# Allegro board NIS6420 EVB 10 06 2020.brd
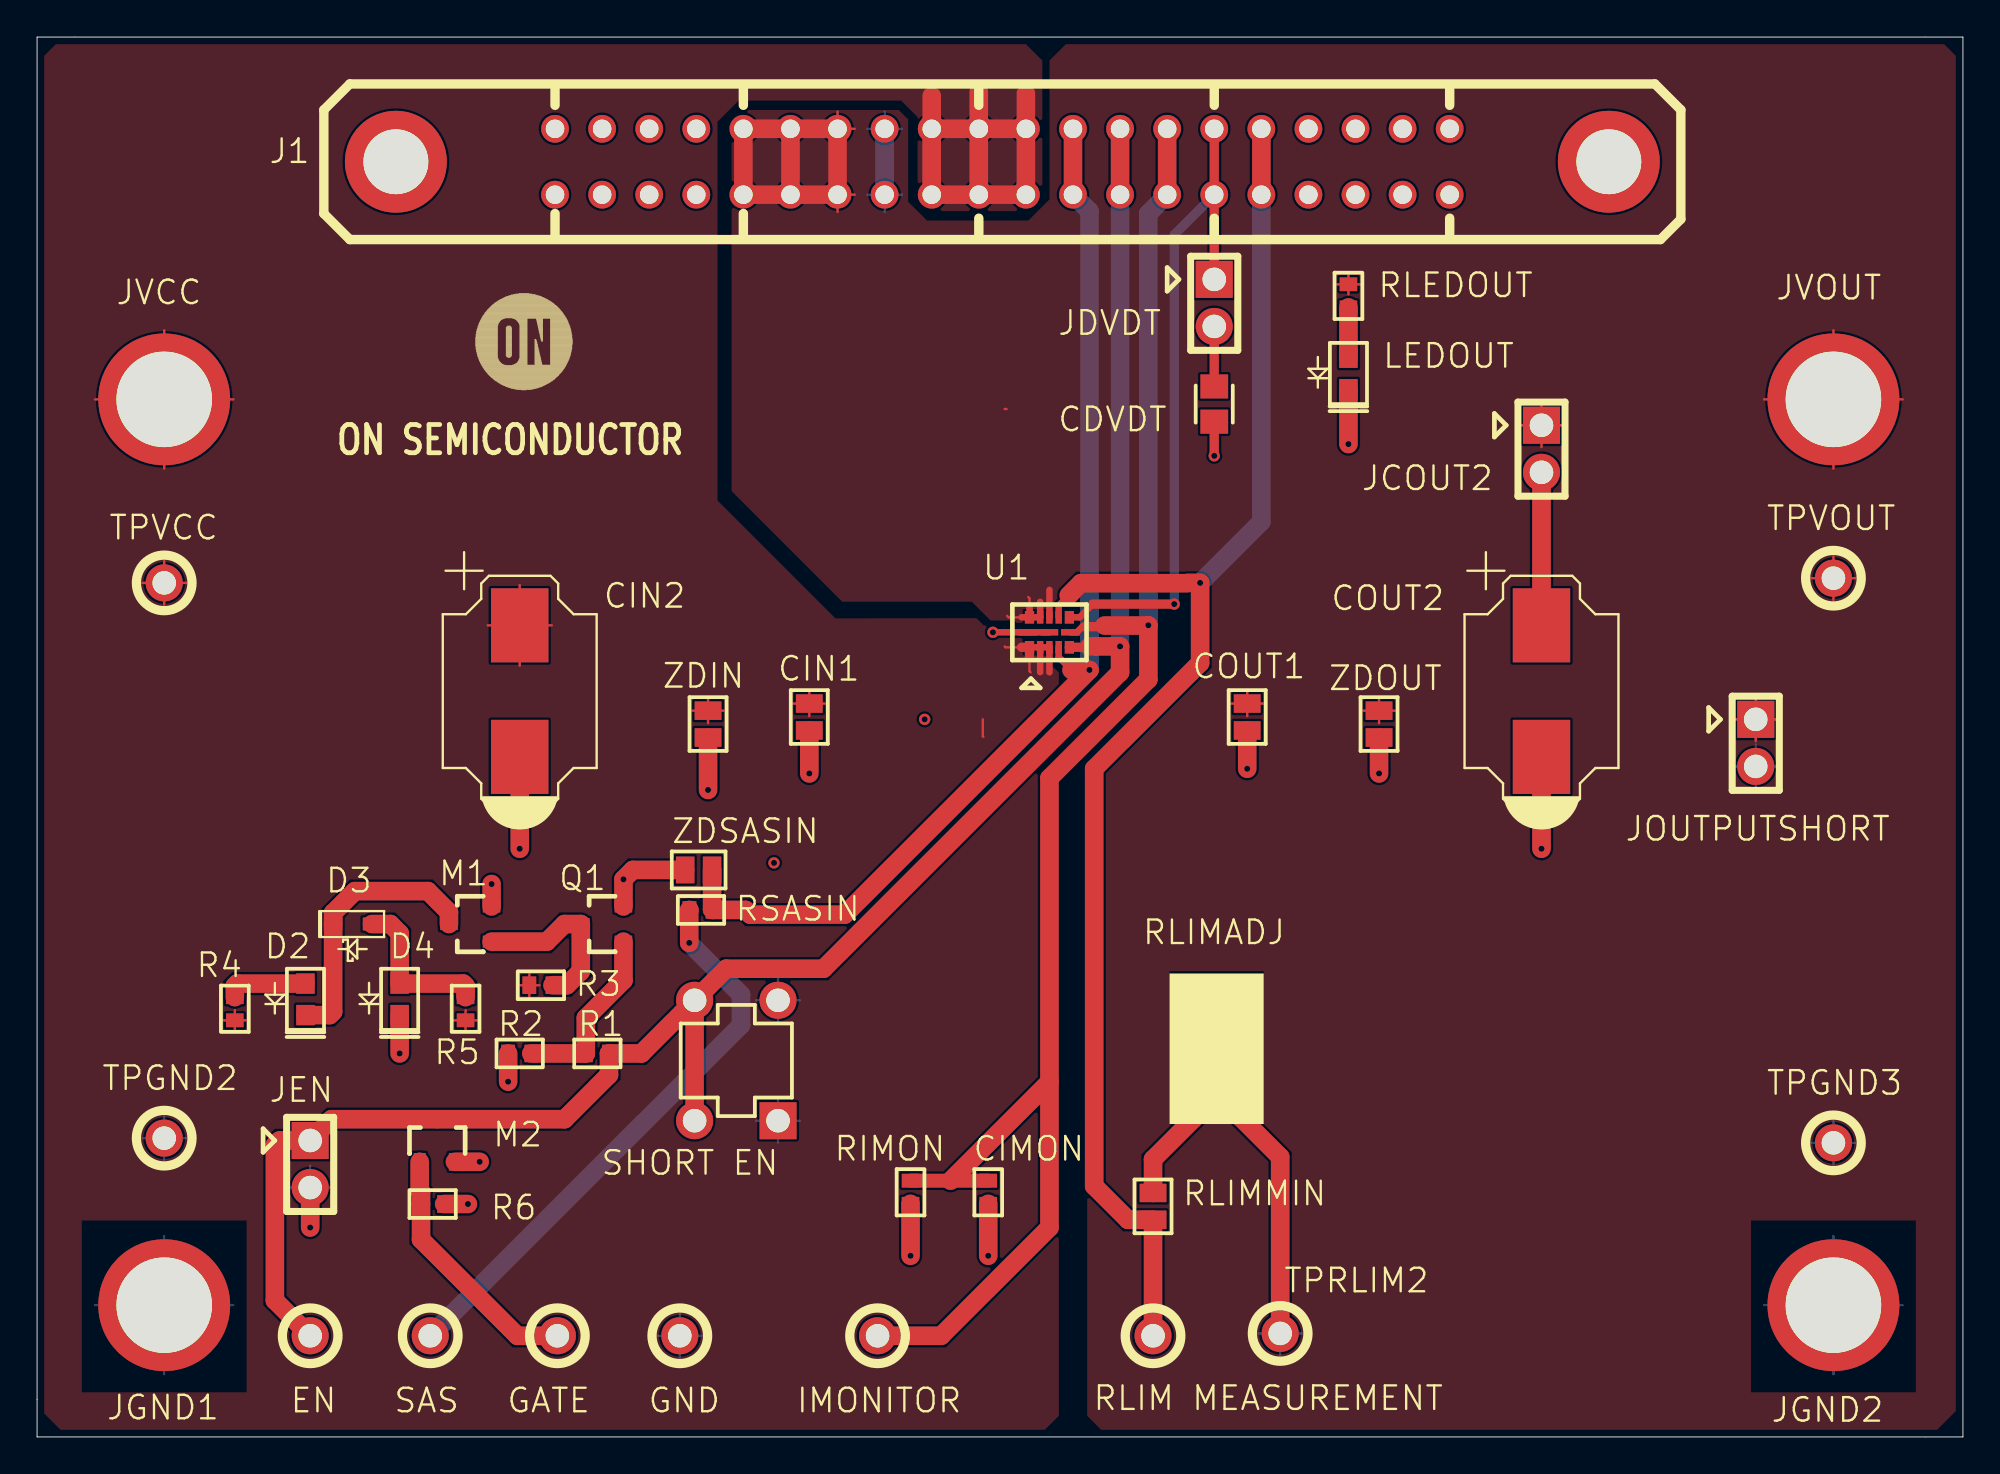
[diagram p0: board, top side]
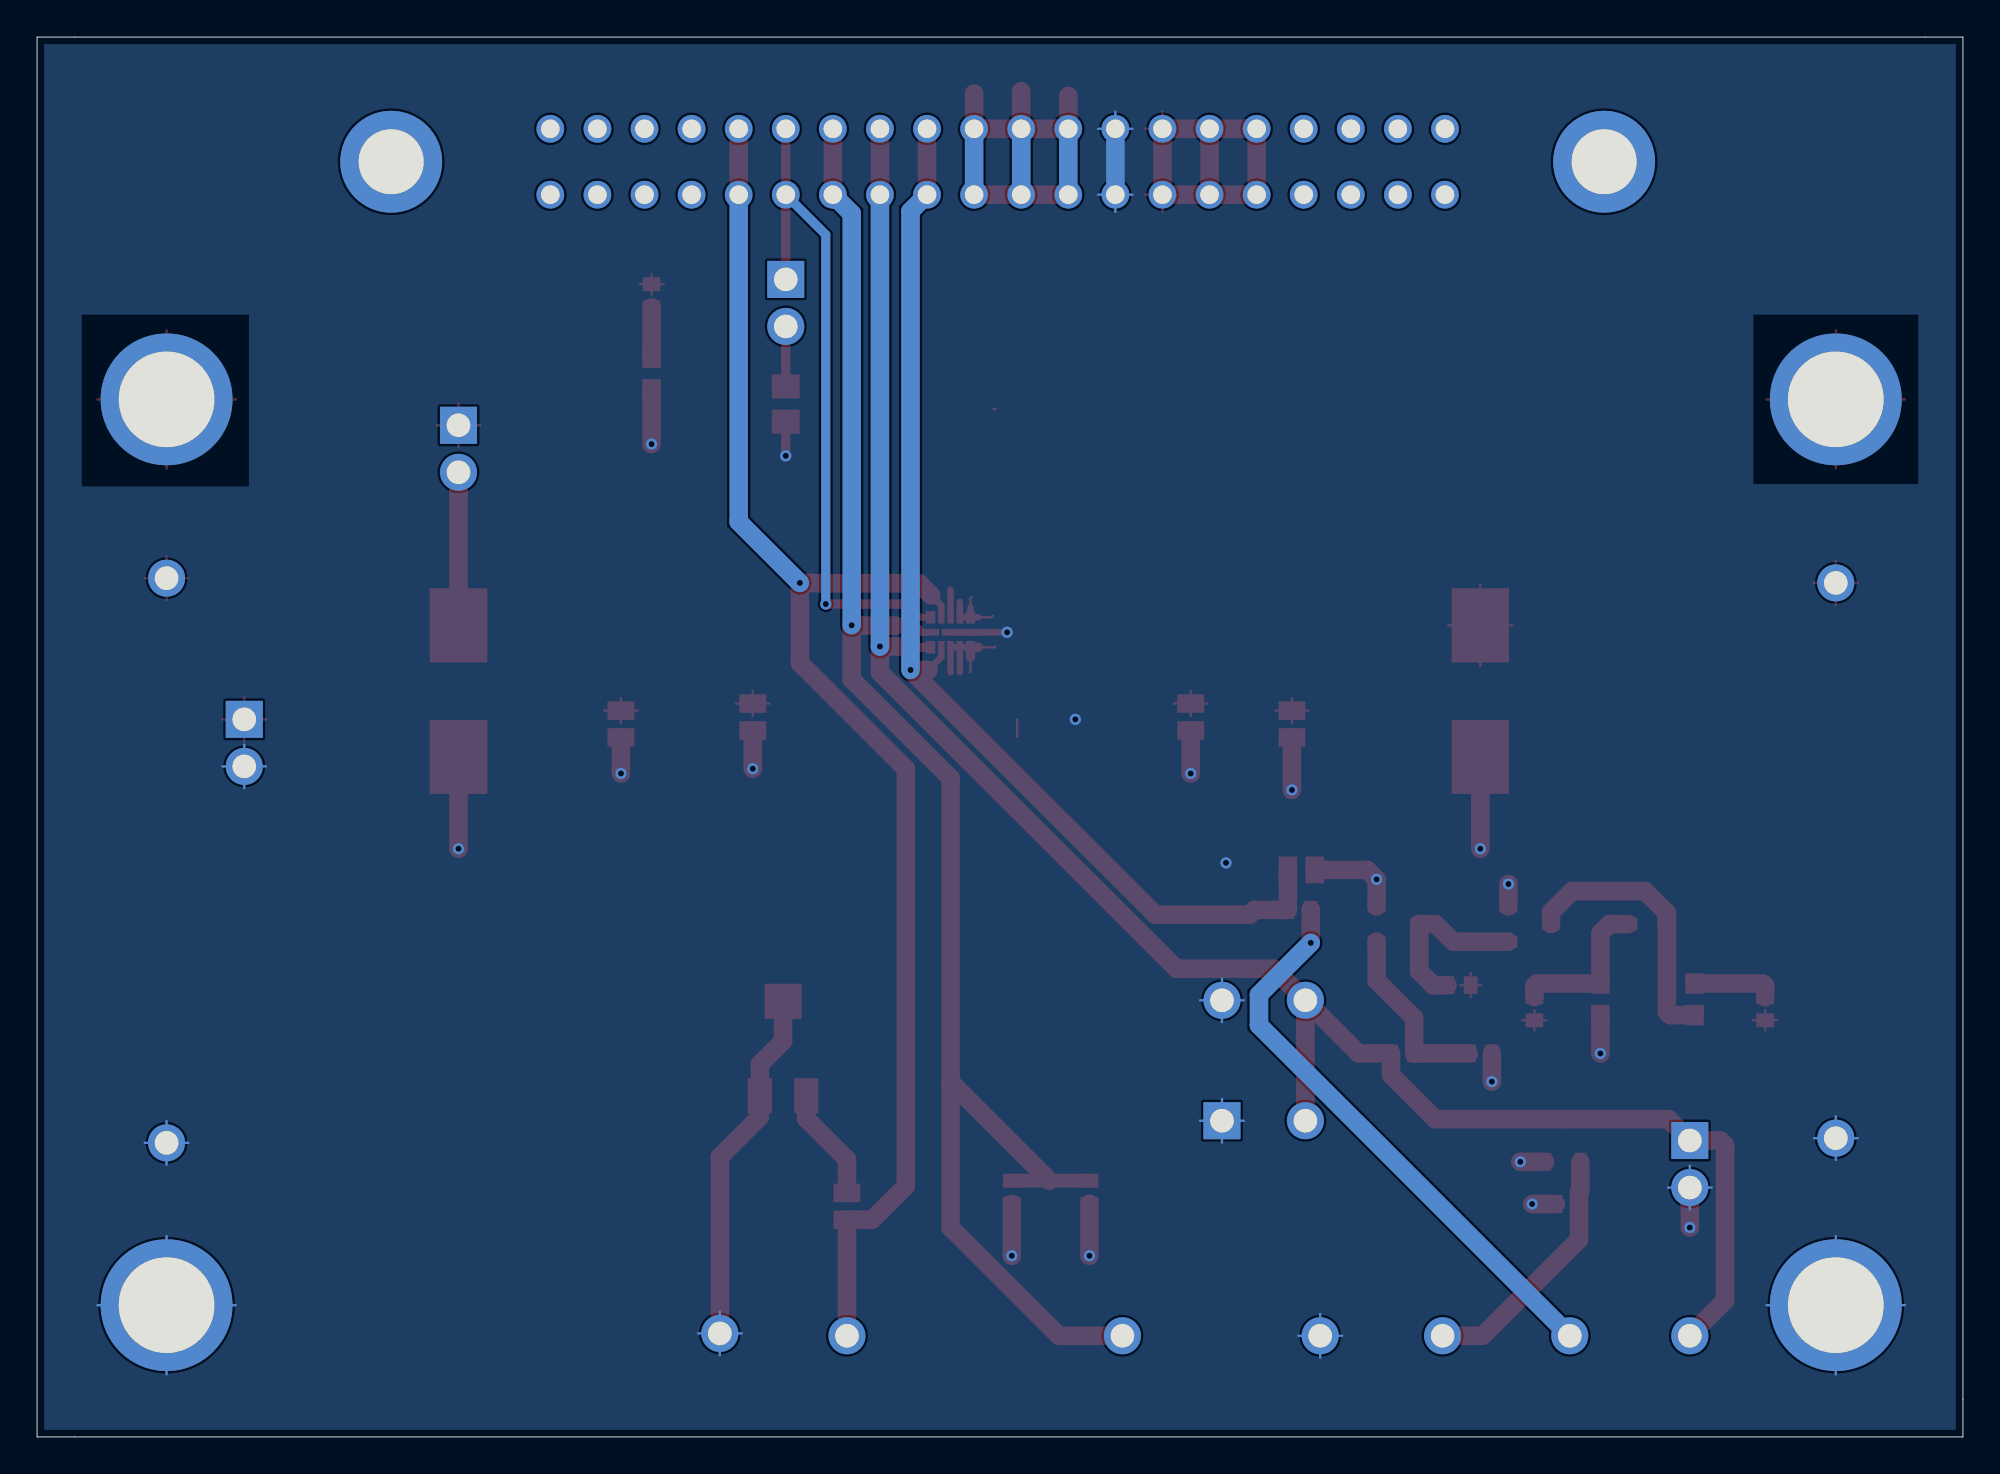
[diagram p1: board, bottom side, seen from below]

Outline 103.89 x 75.56 mm; copper layers: TOP, BOTTOM. Coordinates in mm from the lower left corner of the outline.
Outline path: 0,75.56 103.89,75.56 103.89,0 0,0 0,75.56

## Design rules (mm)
constraint set DEFAULT: min track width 0.127

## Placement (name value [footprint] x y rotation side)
CDVDT  2.2nF  [C0805]  63.5 55.75 270 top
CIMON  0.1uF/50V  [0603]  51.31 13.21 270 top
CIN1  1uF/50V  [0805]  41.66 38.86 270 top
CIN2  56u/35V  [CAP_SMD_8P3X8P3]  26.04 40.26 90 top
COUT1  1uF/50V  [0805]  65.28 38.86 270 top
COUT2  56uF/35V  [CAP_SMD_8P3X8P3]  81.15 40.26 90 top
D2  LED0603-YELLOW  [LED0603]  14.48 23.62 270 top
D3  BAS16H  [SOD-323]  17.02 27.69 180 top
D4  LED0603-GREEN  [LED0603]  19.56 23.62 270 top
EN  -  [unnamed]  14.73 5.46 0 top
GATE  -  [TP-HOOK]  28.07 5.46 0 top
GND  -  [unnamed]  34.67 5.46 0 top
IMONITOR  -  [unnamed]  45.34 5.46 0 top
J1  -  [unnamed#2]  52.07 68.83 90 top
JCOUT2  HDR-2  [HEADER-2]  81.15 53.34 270 top
JDVDT  HDR-2  [HEADER-2]  63.5 61.21 270 top
JEN  -  [unnamed#3]  14.73 14.73 270 top
JGND1  BANANA JACK  [BANANA_VIA]  6.86 7.11 0 top
JGND2  BANANA JACK  [BANANA_VIA]  96.9 7.11 0 top
JOUTPUTSHORT  HDR-2  [HEADER-2]  92.71 37.47 270 top
JVCC  BANANA JACK  [BANANA_VIA]  6.86 56.01 0 top
JVOUT  BANANA JACK  [BANANA_VIA]  96.9 56.01 0 top
LEDOUT  LED0603-GREEN  [LED0603]  70.74 57.4 270 top
M1  2N7002KT1G  [SOT-23]  23.37 27.69 180 top
M2  2N7002KT1G  [SOT-23]  21.59 16 90 top
ON SEMICONDUCTOR  -  [#5]  26.29 59.18 0 top
Q1  MMBT3904LT1G  [SOT-23]  30.48 27.69 180 top
R1  3M  [0603]  30.23 20.7 180 top
R2  1.1M  [0603]  26.04 20.7 180 top
R3  1.1M  [0603]  27.18 24.38 0 top
R4  2.2k  [0603]  10.67 23.11 90 top
R5  10k  [0603]  23.11 23.11 90 top
R6  10k  [0603]  21.34 12.57 0 top
RIMON  1k  [0603]  47.12 13.21 270 top
RLEDOUT  10k  [0603]  70.74 61.59 270 top
RLIM MEASUREMENT  -  [unnamed]  60.2 5.46 0 top
RLIMADJ  50KOhm  [3214X_TRIM_POT]  64.9 18.41 90 top
RLIMMIN  4.99k  [0805]  60.2 12.45 270 top
RSASIN  -  [unnamed#6]  35.81 28.45 0 top
SAS  -  [unnamed]  21.21 5.46 0 top
SHORT EN  -  [unnamed#4]  37.72 20.32 90 top
TPGND2  -  [TP-HOOK]  6.86 16.13 0 top
TPGND3  -  [TP-HOOK]  96.9 15.88 0 top
TPRLIM2  -  [TP-HOOK]  67.06 5.59 0 top
TPVCC  -  [TP-HOOK]  6.86 46.1 0 top
TPVOUT  -  [TP-HOOK]  96.9 46.35 0 top
U1  -  [NIS6452]  54.61 43.43 0 top
ZDIN  DIODE ZENER  [0805]  36.2 38.48 270 top
ZDOUT  DIODE ZENER  [0805]  72.39 38.48 270 top
ZDSASIN  -  [unnamed#7]  35.69 30.61 180 top

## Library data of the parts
CDVDT CIMON CIN1 COUT1 = CAP NP
CIN2 COUT2 = CAP
D2 D4 LEDOUT = LED_0
D3 = DIODE_0
GATE TPGND2 TPGND3 TPRLIM2 TPVCC TPVOUT = TP-HOOK
JCOUT2 JDVDT JOUTPUTSHORT = HEADER 2_1
JGND1 JGND2 JVCC JVOUT = Banana Conn
M1 M2 = MMDF4N01HD/ON_1
Q1 = MMBT3904/SOT
R1-R6 RIMON RLEDOUT RLIMMIN = RESISTOR
RLIMADJ = POT/SM
U1 = NIS6452
ZDIN ZDOUT = DIODE ZENER

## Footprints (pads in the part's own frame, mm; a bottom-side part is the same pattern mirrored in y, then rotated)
0603
  rect 0.749x0.95 smd: 1(-0.625,0) 2(0.625,0)
0805
  rect 1x1.45 smd: 1(-0.725,0) 2(0.725,0)
3214X_TRIM_POT
  rect 1.9x1.3 smd: 1(0,0) 3(0,2.5)
  rect 1.9x2 smd: 2(5.1,1.25)
BANANA_VIA
  round 7.112 hole 5.156: 1(0,0)
C0805
  rect 1.3x1.5 smd: 1(-0.95,0) 2(0.95,0)
CAP_SMD_8P3X8P3
  rect 4x3.1 smd: 1(3.55,0) 2(-3.55,0)
HEADER-2
  rect 2x2 hole 1.27: 1(-1.27,0)
  round 2 hole 1.27: 2(1.27,0)
LED0603
  rect 1.1x1 smd: 1(0.851,0) 2(-0.851,0)
NIS6452
  rect 0.5x0.68 smd: 1(-1.075,-0.81) 5(1.075,-0.81) 6(1.075,0.81) 10(-1.075,0.81)
  rect 0.35x0.68 smd: 2(-0.5,-0.81) 3(0,-0.81) 4(0.5,-0.81) 7(0.5,0.81) 8(0,0.81) 9(-0.5,0.81)
  rect 1.025x0.35 smd: 11(-1.137,0) 13(1.137,0)
  rect 0.95x0.35 smd: 12(0,0)
SOD-323
  rect 1x0.7 smd: 1(-1.05,0) 2(1.05,0)
SOT-23
  rect 0.95x0.65 smd: 1(-1.15,0.95) 2(-1.15,-0.95) 3(1.15,0)
TP-HOOK
  round 2 hole 1.27: 1(0,0)
unnamed
  round 2 hole 1.27: 1(0,0)
unnamed#2
  round 1.5 hole 1: 1(-1.778,24.13) 2(1.778,24.13) 3(-1.778,21.59) 4(1.778,21.59) 5(-1.778,19.05) 6(1.778,19.05) 7(-1.778,16.51) 8(1.778,16.51) 9(-1.778,13.97) 10(1.778,13.97) 11(-1.778,11.43) 12(1.778,11.43) 13(-1.778,8.89) 14(1.778,8.89) 15(-1.778,6.35) 16(1.778,6.35) 17(-1.778,3.81) 18(1.778,3.81) 19(-1.778,1.27) 20(1.778,1.27) 21(-1.778,-1.27) 22(1.778,-1.27) 23(-1.778,-3.81) 24(1.778,-3.81) 25(-1.778,-6.35) 26(1.778,-6.35) 27(-1.778,-8.89) 28(1.778,-8.89) 29(-1.778,-11.43) 30(1.778,-11.43) 31(-1.778,-13.97) 32(1.778,-13.97) 33(-1.778,-16.51) 34(1.778,-16.51) 35(-1.778,-19.05) 36(1.778,-19.05) 37(-1.778,-21.59) 38(1.778,-21.59) 39(-1.778,-24.13) 40(1.778,-24.13)
  round 5.5 hole 3.5: 41(0,32.715) 42(0,-32.715)
unnamed#3
  rect 2x2 hole 1.27: 1(-1.27,0)
  round 2 hole 1.27: 2(1.27,0)
unnamed#4
  rect 2x2 hole 1.27: 1(-3.25,-2.25)
  round 2 hole 1.27: 2(3.25,-2.25) 3(-3.25,2.25) 4(3.25,2.25)
unnamed#6
  rect 0.749x0.95 smd: 1(-0.625,0) 2(0.625,0)
unnamed#7
  rect 1x1.45 smd: 1(-0.725,0) 2(0.725,0)

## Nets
GND: CDVDT.2 CIMON.2 CIN1.2 CIN2.2 COUT1.2 COUT2.2 D4.1(CATHODE) GND.1 J1.15 J1.16 JEN.2 JGND1.1 JGND2.1 JOUTPUTSHORT.2 LEDOUT.1(CATHODE) M1.2(S) M2.2(S) Q1.2(E) R2.2 R6.2 RIMON.2 RLIMADJ.1 RLIMADJ.2(WIPER) SHORT EN.1 SHORT EN.2 TPGND2.1 TPGND3.1 TPRLIM2.1 U1.11 U1.12 ZDIN.2 ZDOUT.2 ZDSASIN.2
VCC: CIN1.1 CIN2.1 J1.17 J1.18 J1.19 J1.20 J1.21 J1.22 JVCC.1 R3.1 R4.1 R5.1 TPVCC.1 U1.1 U1.2 U1.3(VCC3) ZDIN.1(CATHODE)
DVT: J1.29 J1.30 JDVDT.1 U1.6
EN_FAIL: EN.1 J1.25 J1.26 JEN.1 M2.3 R1.1 SHORT EN.3 SHORT EN.4 U1.5
ILIM: J1.31 J1.32 RLIM MEASUREMENT.1 RLIMMIN.2 U1.7
IMON: CIMON.1 IMONITOR.1 J1.27 J1.28 RIMON.1 U1.13
SASIN: J1.23 J1.24 RSASIN.2 U1.4 ZDSASIN.1
VSRC: COUT1.1 J1.9 J1.10 J1.11 J1.12 J1.13 J1.14 JCOUT2.1 JOUTPUTSHORT.1 JVOUT.1 RLEDOUT.1 TPVOUT.1 U1.8 U1.9 U1.10 ZDOUT.1(CATHODE)
N12391538: LEDOUT.2 RLEDOUT.2
N12391596: GATE.1 M2.1 R6.1
N12393096: RLIMADJ.3 RLIMMIN.1
N14398226: M1.1 Q1.3 R3.2
N14398234: D3.1 D4.2 R5.2
N14398270: D2.1(CATHODE) D3.2(K) M1.3
N14398290: Q1.1 R1.2 R2.1
N14404692: COUT2.1 JCOUT2.2
N14424104: CDVDT.1 JDVDT.2
N14438244: RSASIN.1 SAS.1
N143981861: D2.2 R4.2

Pads without a net: J1 1 2 3 4 5 6 7 8 33 34 35 36 37 38 39 40 41 42

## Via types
v1: diameter 0.61, hole 0.33, TOP to BOTTOM, 26 vias

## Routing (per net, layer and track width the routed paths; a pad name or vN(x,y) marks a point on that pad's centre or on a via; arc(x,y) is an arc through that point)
GND: length 143.3
  TOP w0.35: U1.12 U1.11 v1(51.56,43.43)
  TOP w0.5: CDVDT.2 v1(63.5,52.96)
  TOP w1: R2.2 v1(25.41,19.18) ; LEDOUT.1 v1(70.74,53.59) ; D4.1 v1(19.56,20.7) ; R6.2 v1(23.24,12.57) ; ZDIN.2 v1(36.2,34.92) ; ZDSASIN.2 32.14,30.61 v1(31.63,30.1) Q1.2 ; RIMON.2 v1(47.12,9.78) ; CIN1.2 v1(41.66,35.81) ; ZDOUT.2 v1(72.39,35.81) ; M1.2 v1(24.52,29.84) ; COUT2.2 v1(81.15,31.75) ; v1(65.28,36.07) COUT1.2 ; CIMON.2 v1(51.31,9.78) ; 63.65,23.64 RLIMADJ.2 63.65,21.37 64.9,20.12 RLIMADJ.1 64.9,17.27 67.06,15.11 TPRLIM2.1 ; M2.2 v1(23.88,14.85) ; JEN.2 v1(14.73,11.3) ; CIN2.2 v1(26.04,31.75)
  BOTTOM w0.127: 6.86,3.38 JGND1.1 ; JGND1.1 3.12,7.11 ; JGND1.1 10.59,7.11 ; JGND1.1 6.86,10.85 ; 67.06,4.41 TPRLIM2.1 ; TPRLIM2.1 67.06,6.77 ; TPRLIM2.1 65.88,5.59 ; TPRLIM2.1 68.23,5.59 ; 92.71,35.02 JOUTPUTSHORT.2 ; JOUTPUTSHORT.2 91.53,36.2 ; JOUTPUTSHORT.2 93.89,36.2 ; JOUTPUTSHORT.2 92.71,37.37 ; TPGND3.1 98.08,15.88 ; TPGND3.1 95.72,15.88 ; TPGND3.1 96.9,17.05 ; TPGND3.1 96.9,14.7 ; SHORT EN.2 39.97,24.75 ; SHORT EN.2 38.79,23.57 ; SHORT EN.2 41.15,23.57 ; SHORT EN.2 39.97,22.39 ; 34.67,4.28 GND.1 ; GND.1 33.49,5.46 ; GND.1 35.85,5.46 ; GND.1 34.67,6.64 ; JGND2.1 96.9,10.85 ; JGND2.1 100.64,7.11 ; JGND2.1 96.9,3.38 ; JGND2.1 93.17,7.11 ; 6.86,14.95 TPGND2.1 ; TPGND2.1 8.04,16.13 ; TPGND2.1 6.86,17.31 ; TPGND2.1 5.68,16.13 ; J1.16 45.72,71.54 ; J1.16 46.65,70.61 ; J1.16 44.79,70.61 ; 38.79,17.07 SHORT EN.1 ; SHORT EN.1 39.97,15.89 ; SHORT EN.1 41.15,17.07 ; SHORT EN.1 39.97,18.25 ; 44.79,67.06 J1.15 ; J1.15 45.72,66.13 ; J1.15 46.65,67.06 ; JEN.2 15.91,13.46 ; JEN.2 14.73,14.64 ; JEN.2 13.55,13.46 ; JEN.2 14.73,12.28
  BOTTOM w1: J1.15 J1.16
  vias: v1(39.75,30.99) v1(47.88,38.73)
VCC: length 85.7
  TOP w0.127: 26.55,23.73 R3.1 ; R3.1 26,24.38 ; R3.1 26.55,25.04 ; R3.1 27.11,24.38 ; CIN1.1 42.56,39.59 ; CIN1.1 41.66,40.26 ; CIN1.1 41.66,38.91 ; CIN1.1 40.75,39.59 ; 53.11,42.62 52.24,42.62 52.2,42.67 ; ZDIN.1 37.1,39.21 ; ZDIN.1 36.2,39.88 ; ZDIN.1 36.2,38.53 ; ZDIN.1 35.29,39.21 ; TPVCC.1 8.04,46.1 ; TPVCC.1 6.86,47.28 ; TPVCC.1 6.86,44.92 ; TPVCC.1 5.68,46.1 ; R4.1 10.67,23.04 ; R4.1 10.02,22.49 ; R4.1 11.32,22.49 ; R4.1 10.67,21.94 ; 53.59,41.27 53.53,41.33 53.53,42.11 ; JVCC.1 6.86,59.74 ; JVCC.1 3.12,56.01 ; JVCC.1 10.59,56.01 ; JVCC.1 6.86,52.27 ; 24.31,43.81 CIN2.1 ; CIN2.1 27.76,43.81 ; CIN2.1 26.04,41.63 ; CIN2.1 26.04,45.99 ; 23.11,21.94 R5.1 ; R5.1 23.11,23.04 ; R5.1 22.46,22.49 ; R5.1 23.77,22.49 ; 51.04,37.79 51.02,37.82 51.02,38.73 ; 54.1,41.27 54.11,41.28
  TOP w0.35: 54.61,41.27 U1.3 U1.2 ; 54.11,41.28 U1.2 ; U1.2 U1.1
  TOP w0.5: 53.53,42.11 U1.1 53.11,42.62
  TOP w1: J1.18 J1.17 J1.19 ; J1.18 48.26,72.39 ; J1.18 J1.20 ; J1.22 J1.21 J1.19 ; J1.22 J1.20 ; J1.22 53.34,72.52 ; J1.20 J1.19 ; J1.20 50.8,72.64
  BOTTOM w1: J1.20 J1.19 ; J1.22 J1.21 ; J1.18 J1.17
DVT: length 37.1
  TOP w0.35: U1.6 56.24,44.24 56.95,44.96
  TOP w0.5: J1.30 J1.29 JDVDT.1 ; v1(61.34,44.96) 56.95,44.96
  BOTTOM w0.5: v1(61.34,44.96) 61.34,64.9 J1.29
EN_FAIL: length 106.5
  TOP w0.5: U1.5 56.72,42.62 56.77,42.67
  TOP w1: SHORT EN.4 32.6,20.7 R1.1 30.85,19.55 28.46,17.15 M2.3 15.88,17.15 JEN.1 13.08,16 12.83,15.75 12.83,7.37 EN.1 ; SHORT EN.4 37.17,25.27 42.42,25.27 58.42,41.27 v1(58.42,42.67) 58.06,42.67 58.05,42.67 57.12,42.67 57.12,42.67 56.77,42.67 ; SHORT EN.4 SHORT EN.3 ; J1.26 J1.25
  BOTTOM w1: 58.42,42.67 v1(58.42,42.67) J1.25
ILIM: length 79.8
  TOP w0.35: U1.7 55.11,44.89 55.65,45.43
  TOP w0.5: 62.06,46.1 62.04,46.09
  TOP w1: RLIM MEASUREMENT.1 RLIMMIN.2 58.85,11.72 57.02,13.54 57.02,36.07 62.74,41.78 v1(62.74,46.1) 62.06,46.1 ; 55.65,45.43 56.31,46.09 62.04,46.09 ; J1.32 J1.31
  BOTTOM w1: v1(62.74,46.1) 66.04,49.4 J1.31
IMON: length 89.8
  TOP w0.127: 57.53,43.74 57.58,43.8
  TOP w0.35: 59.96,43.8 v1(59.94,43.81) ; 56.51,43.74 56.39,43.74 56.09,43.43 U1.13
  TOP w0.5: 56.51,43.74 57.53,43.74
  TOP w0.75: RIMON.1 CIMON.1
  TOP w1: IMONITOR.1 48.77,5.46 54.61,11.3 54.61,19.17 ; J1.28 J1.27 ; v1(59.94,43.81) 59.94,40.89 54.61,35.56 54.61,19.17 ; 49.28,13.83 54.61,19.17 ; 57.58,43.8 59.96,43.8
  BOTTOM w1: J1.27 59.94,66.04 v1(59.94,43.81)
SASIN: length 60.1
  TOP w0.35: 55.8,41.4 55.11,42.09 U1.4
  TOP w1: J1.24 J1.23 ; 55.8,41.4 v1(56.77,41.4) 43.56,28.19 38.47,28.19 38.22,28.45 RSASIN.2 36.41,28.47 ZDSASIN.1
  BOTTOM w1: J1.23 56.77,66.17 v1(56.77,41.4)
VSRC: length 67.7
  TOP w0.127: 71.49,39.21 ZDOUT.1 ; ZDOUT.1 72.39,39.88 ; ZDOUT.1 73.29,39.21 ; ZDOUT.1 72.39,38.53 ; JOUTPUTSHORT.1 92.71,39.91 ; JOUTPUTSHORT.1 91.53,38.73 ; JOUTPUTSHORT.1 93.89,38.73 ; JOUTPUTSHORT.1 92.71,37.56 ; 44.11,70.61 J1.14 43.18,71.54 ; 64.37,39.59 COUT1.1 ; COUT1.1 66.18,39.59 ; COUT1.1 65.28,38.91 ; COUT1.1 65.28,40.26 ; JCOUT2.1 82.33,54.61 ; JCOUT2.1 81.15,53.43 ; JCOUT2.1 81.15,55.79 ; JCOUT2.1 79.97,54.61 ; 95.72,46.35 TPVOUT.1 ; TPVOUT.1 96.9,45.18 ; TPVOUT.1 96.9,47.53 ; TPVOUT.1 98.08,46.35 ; JVOUT.1 100.64,56.01 ; JVOUT.1 93.17,56.01 ; JVOUT.1 96.9,52.27 ; JVOUT.1 96.9,59.74 ; 44.11,67.06 J1.13 43.18,66.13 ; 52.3,55.49 52.2,55.49 ; 70.74,61.67 RLEDOUT.1 ; RLEDOUT.1 71.39,62.22 ; RLEDOUT.1 70.09,62.22 ; RLEDOUT.1 70.74,62.77 ; 53.11,44.24 52.4,44.24 52.32,44.32 ; 54.1,45.09 54.11,45.08 ; 53.53,44.76 53.53,45.27 53.47,45.34
  TOP w0.35: U1.10 U1.9 54.11,45.08 ; U1.10 53.11,44.24 ; U1.10 53.53,44.76 ; U1.8 54.61,45.72
  TOP w1: J1.12 J1.10 J1.9 J1.11 ; J1.12 J1.14 J1.13 J1.11 ; J1.12 J1.11
N12391538: length 2.7
  TOP w1: RLEDOUT.2 LEDOUT.2
N12391596: length 13.7
  TOP w1: GATE.1 25.91,5.46 20.71,10.66 R6.1 20.71,13.24 20.64,13.31 M2.1
N12393096: length 6.3
  TOP w1: RLIMMIN.1 60.2,14.99 62.4,17.18 62.4,18.54
N14398226: length 9.6
  TOP w1: R3.2 28.57,24.38 29.33,25.14 Q1.3 28.45,27.69 27.5,26.74 M1.1
N14398234: length 8.6
  TOP w1: D3.1 19.06,27.69 19.56,27.19 D4.2 22.99,24.47 23.11,24.35 R5.2
N14398270: length 14.7
  TOP w1: D2.1 15.79,22.77 15.97,22.95 D3.2 15.97,28.29 17.14,29.46 21.08,29.46 22.22,28.33 M1.3
N14398290: length 9.8
  TOP w1: R2.1 R1.2 29.6,22.62 31.63,24.65 Q1.1
N14404692: length 8.3
  TOP w1: COUT2.1 JCOUT2.2
N14424104: length 3.2
  TOP w0.5: JDVDT.2 CDVDT.1
N14438244: length 31.1
  TOP w1: v1(35.18,26.67) 35.18,28.44 RSASIN.1
  BOTTOM w1: v1(35.18,26.67) 37.97,23.88 37.97,22.23 SAS.1
N143981861: length 4.5
  TOP w1: D2.2 10.79,24.47 10.67,24.35 R4.2

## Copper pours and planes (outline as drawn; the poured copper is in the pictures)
GND on BOTTOM: 0.38,75.18 0.38,0.38 103.5,0.38 103.5,75.18 ; 2 cut-outs
VCC on TOP: 52.83,42.8 52.96,42.93 54.61,42.93 54.74,42.8 54.74,41.66 54.61,41.53 52.96,41.53 52.83,41.66
VCC on TOP: 1.02,75.18 53.34,75.18 54.23,74.3 54.23,67.31 53.09,66.17 48.39,66.17 47.5,67.06 47.5,71.25 46.61,72.14 38.99,72.14 37.84,72.13 36.7,70.99 36.7,50.55 43.06,44.19 50.67,44.2 51.05,43.81 52.32,43.81 55.12,41.27 55.12,1.14 54.36,0.38 1.27,0.38 0.38,1.27 0.38,74.55 ; 1 cut-out
VSRC on TOP: 52.58,44.83 54.1,44.83 54.23,44.7 54.23,44.07 54.1,43.94 52.83,43.94 52.58,44.2
VSRC on TOP: 102.87,75.18 55.5,75.18 54.61,74.3 54.61,66.8 53.47,65.66 48.01,65.66 46.99,66.67 46.99,71.12 46.48,71.63 38.35,71.63 37.47,70.74 37.47,51.05 43.43,45.09 50.42,45.09 51.44,44.07 54.74,44.07 56.52,45.85 62.36,45.85 62.36,41.91 56.64,36.2 56.64,1.14 57.4,0.38 102.49,0.38 103.5,1.4 103.5,74.55 ; 2 cut-outs

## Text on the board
XSECTION_CHART: *  SURFACE - AIR 0 MM | L1 TOP CONDUCTOR - COPPER 0.03048 MM | *  DIELECTRIC - FR-4 1.54 MM | L2 BOTTOM CONDUCTOR - COPPER 0.03048 MM | DESIGN CROSS SECTION CHART | ___________________________ | TOTAL THICKNESS 1.60096 MM | 1-2
BODY_CENTER: FIGURE | FINISHED_SIZE | 0.3302 | 1.0 | 1.27 | 3.5 | 5.1562 | DRILL CHART: TOP to BOTTOM | ALL UNITS ARE IN MILLIMETERS | TOLERANCE_DRILL | +0.0/-0.0 | +0.0762/-0.0762 | PLATED | QTY | 56 | 40 | 28 | 2 | 4
